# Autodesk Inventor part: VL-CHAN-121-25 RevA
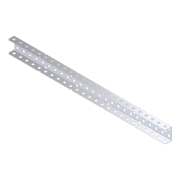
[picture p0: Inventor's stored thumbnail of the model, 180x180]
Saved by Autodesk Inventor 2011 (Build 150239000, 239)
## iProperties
Created: 2007-12
Part Number: VL-CHAN-121-25 RevA
Document SubType Name: Modeling
Density: 1 g/cm^3
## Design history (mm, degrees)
feature "Base1"
sketch "Sketch1"
  geometry: L1 (62.031, 0)-(0, 0) reference; L2 (62.031, 21.438)-(62.031, 0) reference; L3 (0, 21.438)-(62.031, 21.438) reference; L4 (-1.469, 19.794)-(0, 21.438) reference; L5 (-2.937, 21.438)-(-1.469, 19.794) reference; L6 (-63.5, 21.438)-(-2.937, 21.438) reference; L7 (-64.969, 19.794)-(-63.5, 21.438) reference; L8 (-66.437, 21.438)-(-64.969, 19.794) reference; L9 (-127, 21.438)-(-66.437, 21.438) reference; L10 (-128.469, 19.794)-(-127, 21.438) reference; L11 (-129.937, 21.438)-(-128.469, 19.794) reference; L12 (-190.5, 21.438)-(-129.937, 21.438) reference; L13 (-191.969, 19.794)-(-190.5, 21.438) reference; L14 (-193.437, 21.438)-(-191.969, 19.794) reference; L15 (-255.469, 21.438)-(-193.437, 21.438) reference; L16 (-255.469, 0)-(-255.469, 21.438) reference; L17 (-193.437, 0)-(-255.469, 0) reference; L18 (-191.969, 1.643)-(-193.437, 0) reference; L19 (-190.5, 0)-(-191.969, 1.643) reference; L20 (-129.937, 0)-(-190.5, 0) reference; L21 (-128.469, 1.643)-(-129.937, 0) reference; L22 (-127, 0)-(-128.469, 1.643) reference; L23 (-66.437, 0)-(-127, 0) reference; L24 (-64.969, 1.643)-(-66.437, 0) reference; L25 (-63.5, 0)-(-64.969, 1.643) reference; L26 (-2.937, 0)-(-63.5, 0) reference; L27 (-1.469, 1.643)-(-2.937, 0) reference; L28 (0, 0)-(-1.469, 1.643) reference; L29 (51.135, 13.03)-(47.528, 13.03) reference; L30 (51.643, 8.915)-(51.643, 12.522) reference; L31 (47.528, 8.407)-(51.135, 8.407) reference; L32 (47.02, 12.522)-(47.02, 8.915) reference; L33 (38.435, 13.03)-(34.828, 13.03) reference; L34 (38.943, 8.915)-(38.943, 12.522) reference; L35 (34.828, 8.407)-(38.435, 8.407) reference; L36 (34.32, 12.522)-(34.32, 8.915) reference; L37 (25.735, 13.03)-(22.128, 13.03) reference; L38 (26.243, 8.915)-(26.243, 12.522) reference; L39 (22.128, 8.407)-(25.735, 8.407) reference; L40 (21.62, 12.522)-(21.62, 8.915) reference; L41 (13.035, 13.03)-(9.428, 13.03) reference; L42 (13.543, 8.915)-(13.543, 12.522) reference; L43 (9.428, 8.407)-(13.035, 8.407) reference; L44 (8.92, 12.522)-(8.92, 8.915) reference; L45 (0.335, 13.03)-(-3.272, 13.03) reference; L46 (0.843, 8.915)-(0.843, 12.522) reference; L47 (-3.272, 8.407)-(0.335, 8.407) reference; L48 (-3.78, 12.522)-(-3.78, 8.915) reference; L49 (-12.365, 13.03)-(-15.972, 13.03) reference; L50 (-11.857, 8.915)-(-11.857, 12.522) reference; L51 (-15.972, 8.407)-(-12.365, 8.407) reference; L52 (-16.48, 12.522)-(-16.48, 8.915) reference; L53 (-25.065, 13.03)-(-28.672, 13.03) reference; L54 (-24.557, 8.915)-(-24.557, 12.522) reference; L55 (-28.672, 8.407)-(-25.065, 8.407) reference; L56 (-29.18, 12.522)-(-29.18, 8.915) reference; L57 (-37.765, 13.03)-(-41.372, 13.03) reference; L58 (-37.257, 8.915)-(-37.257, 12.522) reference; L59 (-41.372, 8.407)-(-37.765, 8.407) reference; L60 (-41.88, 12.522)-(-41.88, 8.915) reference; L61 (-50.465, 13.03)-(-54.072, 13.03) reference; L62 (-49.957, 8.915)-(-49.957, 12.522) reference; L63 (-54.072, 8.407)-(-50.465, 8.407) reference; L64 (-54.58, 12.522)-(-54.58, 8.915) reference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; C1 r 2.311 at (49.331, 10.719); C2 r 2.311 at (36.631, 10.719); C3 r 2.311 at (23.931, 10.719); C4 r 2.311 at (11.231, 10.719); C5 r 2.311 at (-1.469, 10.719); C6 r 2.311 at (-14.169, 10.719); C7 r 2.311 at (-26.869, 10.719); C8 r 2.311 at (-39.569, 10.719); C9 r 2.311 at (-52.269, 10.719); C10 r 2.311 at (-64.969, 10.719); C11 r 2.311 at (-77.669, 10.719); C12 r 2.311 at (-90.369, 10.719); C13 r 2.311 at (-103.069, 10.719); C14 r 2.311 at (-115.769, 10.719); C15 r 2.311 at (-128.469, 10.719); C16 r 2.311 at (-141.169, 10.719); C17 r 2.311 at (-153.869, 10.719); C18 r 2.311 at (-166.569, 10.719); C19 r 2.311 at (-179.269, 10.719); C20 r 2.311 at (-191.969, 10.719); C21 r 2.311 at (-204.669, 10.719); C22 r 2.311 at (-217.369, 10.719); C23 r 2.311 at (-230.069, 10.719); C24 r 2.311 at (-242.769, 10.719); A1 r 0.508 centre (47.528, 12.522) between (47.528, 13.03) and (47.02, 12.522) reference; A2 r 0.508 centre (51.135, 12.522) between (51.643, 12.522) and (51.135, 13.03) reference; A3 r 0.508 centre (51.135, 8.915) between (51.135, 8.407) and (51.643, 8.915) reference; A4 r 0.508 centre (47.528, 8.915) between (47.02, 8.915) and (47.528, 8.407) reference; A5 r 0.508 centre (34.828, 12.522) between (34.828, 13.03) and (34.32, 12.522) reference; A6 r 0.508 centre (38.435, 12.522) between (38.943, 12.522) and (38.435, 13.03) reference; A7 r 0.508 centre (38.435, 8.915) between (38.435, 8.407) and (38.943, 8.915) reference; A8 r 0.508 centre (34.828, 8.915) between (34.32, 8.915) and (34.828, 8.407) reference; A9 r 0.508 centre (22.128, 12.522) between (22.128, 13.03) and (21.62, 12.522) reference; A10 r 0.508 centre (25.735, 12.522) between (26.243, 12.522) and (25.735, 13.03) reference; A11 r 0.508 centre (25.735, 8.915) between (25.735, 8.407) and (26.243, 8.915) reference; A12 r 0.508 centre (22.128, 8.915) between (21.62, 8.915) and (22.128, 8.407) reference; A13 r 0.508 centre (9.428, 12.522) between (9.428, 13.03) and (8.92, 12.522) reference; A14 r 0.508 centre (13.035, 12.522) between (13.543, 12.522) and (13.035, 13.03) reference; A15 r 0.508 centre (13.035, 8.915) between (13.035, 8.407) and (13.543, 8.915) reference; A16 r 0.508 centre (9.428, 8.915) between (8.92, 8.915) and (9.428, 8.407) reference; A17 r 0.508 centre (-3.272, 12.522) between (-3.272, 13.03) and (-3.78, 12.522) reference; A18 r 0.508 centre (0.335, 12.522) between (0.843, 12.522) and (0.335, 13.03) reference; A19 r 0.508 centre (0.335, 8.915) between (0.335, 8.407) and (0.843, 8.915) reference; A20 r 0.508 centre (-3.272, 8.915) between (-3.78, 8.915) and (-3.272, 8.407) reference; A21 r 0.508 centre (-15.972, 12.522) between (-15.972, 13.03) and (-16.48, 12.522) reference; A22 r 0.508 centre (-12.365, 12.522) between (-11.857, 12.522) and (-12.365, 13.03) reference; A23 r 0.508 centre (-12.365, 8.915) between (-12.365, 8.407) and (-11.857, 8.915) reference; A24 r 0.508 centre (-15.972, 8.915) between (-16.48, 8.915) and (-15.972, 8.407) reference; A25 r 0.508 centre (-28.672, 12.522) between (-28.672, 13.03) and (-29.18, 12.522) reference; A26 r 0.508 centre (-25.065, 12.522) between (-24.557, 12.522) and (-25.065, 13.03) reference; A27 r 0.508 centre (-25.065, 8.915) between (-25.065, 8.407) and (-24.557, 8.915) reference; A28 r 0.508 centre (-28.672, 8.915) between (-29.18, 8.915) and (-28.672, 8.407) reference; A29 r 0.508 centre (-41.372, 12.522) between (-41.372, 13.03) and (-41.88, 12.522) reference; A30 r 0.508 centre (-37.765, 12.522) between (-37.257, 12.522) and (-37.765, 13.03) reference; A31 r 0.508 centre (-37.765, 8.915) between (-37.765, 8.407) and (-37.257, 8.915) reference; A32 r 0.508 centre (-41.372, 8.915) between (-41.88, 8.915) and (-41.372, 8.407) reference; A33 r 0.508 centre (-54.072, 12.522) between (-54.072, 13.03) and (-54.58, 12.522) reference; A34 r 0.508 centre (-50.465, 12.522) between (-49.957, 12.522) and (-50.465, 13.03) reference; A35 r 0.508 centre (-50.465, 8.915) between (-50.465, 8.407) and (-49.957, 8.915) reference; A36 r 0.508 centre (-54.072, 8.915) between (-54.58, 8.915) and (-54.072, 8.407) reference; A37 r 0.508 centre (-66.772, 12.522) between (-66.772, 13.03) and (-67.28, 12.522) reference; A38 r 0.508 centre (-63.165, 12.522) between (-62.657, 12.522) and (-63.165, 13.03) reference; A39 r 0.508 centre (-63.165, 8.915) between (-63.165, 8.407) and (-62.657, 8.915) reference; A40 r 0.508 centre (-66.772, 8.915) between (-67.28, 8.915) and (-66.772, 8.407) reference; A41 r 0.508 centre (-79.472, 12.522) between (-79.472, 13.03) and (-79.98, 12.522) reference; A42 r 0.508 centre (-75.865, 12.522) between (-75.357, 12.522) and (-75.865, 13.03) reference; A43 r 0.508 centre (-75.865, 8.915) between (-75.865, 8.407) and (-75.357, 8.915) reference; A44 r 0.508 centre (-79.472, 8.915) between (-79.98, 8.915) and (-79.472, 8.407) reference; A45 r 0.508 centre (-92.172, 12.522) between (-92.172, 13.03) and (-92.68, 12.522) reference; A46 r 0.508 centre (-88.565, 12.522) between (-88.057, 12.522) and (-88.565, 13.03) reference; A47 r 0.508 centre (-88.565, 8.915) between (-88.565, 8.407) and (-88.057, 8.915) reference; A48 r 0.508 centre (-92.172, 8.915) between (-92.68, 8.915) and (-92.172, 8.407) reference; A49 r 0.508 centre (-104.872, 12.522) between (-104.872, 13.03) and (-105.38, 12.522) reference; A50 r 0.508 centre (-101.265, 12.522) between (-100.757, 12.522) and (-101.265, 13.03) reference; A51 r 0.508 centre (-101.265, 8.915) between (-101.265, 8.407) and (-100.757, 8.915) reference; A52 r 0.508 centre (-104.872, 8.915) between (-105.38, 8.915) and (-104.872, 8.407) reference; A53 r 0.508 centre (-117.572, 12.522) between (-117.572, 13.03) and (-118.08, 12.522) reference; A54 r 0.508 centre (-113.965, 12.522) between (-113.457, 12.522) and (-113.965, 13.03) reference; A55 r 0.508 centre (-113.965, 8.915) between (-113.965, 8.407) and (-113.457, 8.915) reference; A56 r 0.508 centre (-117.572, 8.915) between (-118.08, 8.915) and (-117.572, 8.407) reference; A57 r 0.508 centre (-130.272, 12.522) between (-130.272, 13.03) and (-130.78, 12.522) reference; A58 r 0.508 centre (-126.665, 12.522) between (-126.157, 12.522) and (-126.665, 13.03) reference; A59 r 0.508 centre (-126.665, 8.915) between (-126.665, 8.407) and (-126.157, 8.915) reference; A60 r 0.508 centre (-130.272, 8.915) between (-130.78, 8.915) and (-130.272, 8.407) reference; A61 r 0.508 centre (-142.972, 12.522) between (-142.972, 13.03) and (-143.48, 12.522) reference; A62 r 0.508 centre (-139.365, 12.522) between (-138.857, 12.522) and (-139.365, 13.03) reference; A63 r 0.508 centre (-139.365, 8.915) between (-139.365, 8.407) and (-138.857, 8.915) reference; A64 r 0.508 centre (-142.972, 8.915) between (-143.48, 8.915) and (-142.972, 8.407) reference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
  constraints: 24 centre point, 3 tangent, 1 horizontal, 46 other
  dimensions: "d2" = 12.7 distance of C1.centre C2.centre
sketch "Sketch2" dims "d12" = 25.4
  geometry: L1 (-1.469, -9.86)-(0.558, -11.887) reference; L2 (0.558, -11.887)-(60.406, -11.887) reference; L3 (60.406, -11.887)-(62.031, -10.262) reference; L4 (62.031, -10.262)-(62.031, 0) reference; L5 (0, 0)-(62.031, 0) reference; L6 (-1.469, -1.643)-(0, 0) reference; L7 (-1.469, -1.643)-(-2.937, 0) reference; L8 (-63.5, 0)-(-2.937, 0) reference; L9 (-64.969, -1.643)-(-63.5, 0) reference; L10 (-64.969, -1.643)-(-66.437, 0) reference; L11 (-127, 0)-(-66.437, 0) reference; L12 (-128.469, -1.643)-(-127, 0) reference; L13 (-129.937, 0)-(-128.469, -1.643) reference; L14 (-190.5, 0)-(-129.937, 0) reference; L15 (-191.969, -1.643)-(-190.5, 0) reference; L16 (-191.969, -1.643)-(-193.437, 0) reference; L17 (-255.469, 0)-(-193.437, 0) reference; L18 (-255.469, 0)-(-255.469, -10.262) reference; L19 (-255.469, -10.262)-(-253.843, -11.887) reference; L20 (-253.843, -11.887)-(-193.995, -11.887) reference; L21 (-191.969, -9.86)-(-193.995, -11.887) reference; L22 (-191.969, -9.86)-(-189.942, -11.887) reference; L23 (-189.942, -11.887)-(-130.495, -11.887) reference; L24 (-128.469, -9.86)-(-130.495, -11.887) reference; L25 (-126.442, -11.887)-(-128.469, -9.86) reference; L26 (-126.442, -11.887)-(-66.995, -11.887) reference; L27 (-64.969, -9.86)-(-66.995, -11.887) reference; L28 (-64.969, -9.86)-(-62.942, -11.887) reference; L29 (-62.942, -11.887)-(-3.495, -11.887) reference; L30 (-1.469, -9.86)-(-3.495, -11.887) reference; L31 (-251.43, -7.341)-(-251.43, -3.734) reference; L32 (-250.922, -3.226)-(-247.315, -3.226) reference; L33 (-246.807, -3.734)-(-246.807, -7.341) reference; L34 (-247.315, -7.849)-(-250.922, -7.849) reference; L35 (-238.73, -7.341)-(-238.73, -3.734) reference; L36 (-238.222, -3.226)-(-234.615, -3.226) reference; L37 (-234.107, -3.734)-(-234.107, -7.341) reference; L38 (-234.615, -7.849)-(-238.222, -7.849) reference; L39 (-226.03, -7.341)-(-226.03, -3.734) reference; L40 (-225.522, -3.226)-(-221.915, -3.226) reference; L41 (-221.407, -3.734)-(-221.407, -7.341) reference; L42 (-221.915, -7.849)-(-225.522, -7.849) reference; L43 (-213.33, -7.341)-(-213.33, -3.734) reference; L44 (-212.822, -3.226)-(-209.215, -3.226) reference; L45 (-208.707, -3.734)-(-208.707, -7.341) reference; L46 (-209.215, -7.849)-(-212.822, -7.849) reference; L47 (-200.63, -7.341)-(-200.63, -3.734) reference; L48 (-200.122, -3.226)-(-196.515, -3.226) reference; L49 (-196.007, -3.734)-(-196.007, -7.341) reference; L50 (-196.515, -7.849)-(-200.122, -7.849) reference; L51 (-187.93, -7.341)-(-187.93, -3.734) reference; L52 (-187.422, -3.226)-(-183.815, -3.226) reference; L53 (-183.307, -3.734)-(-183.307, -7.341) reference; L54 (-183.815, -7.849)-(-187.422, -7.849) reference; L55 (-175.23, -7.341)-(-175.23, -3.734) reference; L56 (-174.722, -3.226)-(-171.115, -3.226) reference; L57 (-170.607, -3.734)-(-170.607, -7.341) reference; L58 (-171.115, -7.849)-(-174.722, -7.849) reference; L59 (-162.53, -7.341)-(-162.53, -3.734) reference; L60 (-162.022, -3.226)-(-158.415, -3.226) reference; L61 (-157.907, -3.734)-(-157.907, -7.341) reference; L62 (-158.415, -7.849)-(-162.022, -7.849) reference; L63 (-149.83, -7.341)-(-149.83, -3.734) reference; L64 (-149.322, -3.226)-(-145.715, -3.226) reference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; C1 r 2.311 at (55.681, -5.537); C2 r 2.311 at (42.981, -5.537); C3 r 2.311 at (30.281, -5.537); C4 r 2.311 at (17.581, -5.537); C5 r 2.311 at (4.881, -5.537); C6 r 2.311 at (-7.819, -5.537); C7 r 2.311 at (-20.519, -5.537); C8 r 2.311 at (-33.219, -5.537); C9 r 2.311 at (-45.919, -5.537); C10 r 2.311 at (-58.619, -5.537); C11 r 2.311 at (-71.319, -5.537); C12 r 2.311 at (-84.019, -5.537); C13 r 2.311 at (-96.719, -5.537); C14 r 2.311 at (-109.419, -5.537); C15 r 2.311 at (-122.119, -5.537); C16 r 2.311 at (-134.819, -5.537); C17 r 2.311 at (-147.519, -5.537); C18 r 2.311 at (-160.219, -5.537); C19 r 2.311 at (-172.919, -5.537); C20 r 2.311 at (-185.619, -5.537); C21 r 2.311 at (-198.319, -5.537); C22 r 2.311 at (-211.019, -5.537); C23 r 2.311 at (-223.719, -5.537); C24 r 2.311 at (-236.419, -5.537); C25 r 2.311 at (-249.119, -5.537); A1 r 0.508 centre (-250.922, -7.341) between (-251.43, -7.341) and (-250.922, -7.849) reference; A2 r 0.508 centre (-250.922, -3.734) between (-250.922, -3.226) and (-251.43, -3.734) reference; A3 r 0.508 centre (-247.315, -3.734) between (-246.807, -3.734) and (-247.315, -3.226) reference; A4 r 0.508 centre (-247.315, -7.341) between (-247.315, -7.849) and (-246.807, -7.341) reference; A5 r 0.508 centre (-238.222, -7.341) between (-238.73, -7.341) and (-238.222, -7.849) reference; A6 r 0.508 centre (-238.222, -3.734) between (-238.222, -3.226) and (-238.73, -3.734) reference; A7 r 0.508 centre (-234.615, -3.734) between (-234.107, -3.734) and (-234.615, -3.226) reference; A8 r 0.508 centre (-234.615, -7.341) between (-234.615, -7.849) and (-234.107, -7.341) reference; A9 r 0.508 centre (-225.522, -7.341) between (-226.03, -7.341) and (-225.522, -7.849) reference; A10 r 0.508 centre (-225.522, -3.734) between (-225.522, -3.226) and (-226.03, -3.734) reference; A11 r 0.508 centre (-221.915, -3.734) between (-221.407, -3.734) and (-221.915, -3.226) reference; A12 r 0.508 centre (-221.915, -7.341) between (-221.915, -7.849) and (-221.407, -7.341) reference; A13 r 0.508 centre (-212.822, -7.341) between (-213.33, -7.341) and (-212.822, -7.849) reference; A14 r 0.508 centre (-212.822, -3.734) between (-212.822, -3.226) and (-213.33, -3.734) reference; A15 r 0.508 centre (-209.215, -3.734) between (-208.707, -3.734) and (-209.215, -3.226) reference; A16 r 0.508 centre (-209.215, -7.341) between (-209.215, -7.849) and (-208.707, -7.341) reference; A17 r 0.508 centre (-200.122, -7.341) between (-200.63, -7.341) and (-200.122, -7.849) reference; A18 r 0.508 centre (-200.122, -3.734) between (-200.122, -3.226) and (-200.63, -3.734) reference; A19 r 0.508 centre (-196.515, -3.734) between (-196.007, -3.734) and (-196.515, -3.226) reference; A20 r 0.508 centre (-196.515, -7.341) between (-196.515, -7.849) and (-196.007, -7.341) reference; A21 r 0.508 centre (-187.422, -7.341) between (-187.93, -7.341) and (-187.422, -7.849) reference; A22 r 0.508 centre (-187.422, -3.734) between (-187.422, -3.226) and (-187.93, -3.734) reference; A23 r 0.508 centre (-183.815, -3.734) between (-183.307, -3.734) and (-183.815, -3.226) reference; A24 r 0.508 centre (-183.815, -7.341) between (-183.815, -7.849) and (-183.307, -7.341) reference; A25 r 0.508 centre (-174.722, -7.341) between (-175.23, -7.341) and (-174.722, -7.849) reference; A26 r 0.508 centre (-174.722, -3.734) between (-174.722, -3.226) and (-175.23, -3.734) reference; A27 r 0.508 centre (-171.115, -3.734) between (-170.607, -3.734) and (-171.115, -3.226) reference; A28 r 0.508 centre (-171.115, -7.341) between (-171.115, -7.849) and (-170.607, -7.341) reference; A29 r 0.508 centre (-162.022, -7.341) between (-162.53, -7.341) and (-162.022, -7.849) reference; A30 r 0.508 centre (-162.022, -3.734) between (-162.022, -3.226) and (-162.53, -3.734) reference; A31 r 0.508 centre (-158.415, -3.734) between (-157.907, -3.734) and (-158.415, -3.226) reference; A32 r 0.508 centre (-158.415, -7.341) between (-158.415, -7.849) and (-157.907, -7.341) reference; A33 r 0.508 centre (-149.322, -7.341) between (-149.83, -7.341) and (-149.322, -7.849) reference; A34 r 0.508 centre (-149.322, -3.734) between (-149.322, -3.226) and (-149.83, -3.734) reference; A35 r 0.508 centre (-145.715, -3.734) between (-145.207, -3.734) and (-145.715, -3.226) reference; A36 r 0.508 centre (-145.715, -7.341) between (-145.715, -7.849) and (-145.207, -7.341) reference; A37 r 0.508 centre (-136.622, -7.341) between (-137.13, -7.341) and (-136.622, -7.849) reference; A38 r 0.508 centre (-136.622, -3.734) between (-136.622, -3.226) and (-137.13, -3.734) reference; A39 r 0.508 centre (-133.015, -3.734) between (-132.507, -3.734) and (-133.015, -3.226) reference; A40 r 0.508 centre (-133.015, -7.341) between (-133.015, -7.849) and (-132.507, -7.341) reference; A41 r 0.508 centre (-123.922, -7.341) between (-124.43, -7.341) and (-123.922, -7.849) reference; A42 r 0.508 centre (-123.922, -3.734) between (-123.922, -3.226) and (-124.43, -3.734) reference; A43 r 0.508 centre (-120.315, -3.734) between (-119.807, -3.734) and (-120.315, -3.226) reference; A44 r 0.508 centre (-120.315, -7.341) between (-120.315, -7.849) and (-119.807, -7.341) reference; A45 r 0.508 centre (-111.222, -7.341) between (-111.73, -7.341) and (-111.222, -7.849) reference; A46 r 0.508 centre (-111.222, -3.734) between (-111.222, -3.226) and (-111.73, -3.734) reference; A47 r 0.508 centre (-107.615, -3.734) between (-107.107, -3.734) and (-107.615, -3.226) reference; A48 r 0.508 centre (-107.615, -7.341) between (-107.615, -7.849) and (-107.107, -7.341) reference; A49 r 0.508 centre (-98.522, -7.341) between (-99.03, -7.341) and (-98.522, -7.849) reference; A50 r 0.508 centre (-98.522, -3.734) between (-98.522, -3.226) and (-99.03, -3.734) reference; A51 r 0.508 centre (-94.915, -3.734) between (-94.407, -3.734) and (-94.915, -3.226) reference; A52 r 0.508 centre (-94.915, -7.341) between (-94.915, -7.849) and (-94.407, -7.341) reference; A53 r 0.508 centre (-85.822, -7.341) between (-86.33, -7.341) and (-85.822, -7.849) reference; A54 r 0.508 centre (-85.822, -3.734) between (-85.822, -3.226) and (-86.33, -3.734) reference; A55 r 0.508 centre (-82.215, -3.734) between (-81.707, -3.734) and (-82.215, -3.226) reference; A56 r 0.508 centre (-82.215, -7.341) between (-82.215, -7.849) and (-81.707, -7.341) reference; A57 r 0.508 centre (-73.122, -7.341) between (-73.63, -7.341) and (-73.122, -7.849) reference; A58 r 0.508 centre (-73.122, -3.734) between (-73.122, -3.226) and (-73.63, -3.734) reference; A59 r 0.508 centre (-69.515, -3.734) between (-69.007, -3.734) and (-69.515, -3.226) reference; A60 r 0.508 centre (-69.515, -7.341) between (-69.515, -7.849) and (-69.007, -7.341) reference; A61 r 0.508 centre (-60.422, -7.341) between (-60.93, -7.341) and (-60.422, -7.849) reference; A62 r 0.508 centre (-60.422, -3.734) between (-60.422, -3.226) and (-60.93, -3.734) reference; A63 r 0.508 centre (-56.815, -3.734) between (-56.307, -3.734) and (-56.815, -3.226) reference; A64 r 0.508 centre (-56.815, -7.341) between (-56.815, -7.849) and (-56.307, -7.341) reference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
  constraints: 25 centre point, 7 tangent, 1 horizontal, 46 other
  dimensions: "d9" = 12.7 distance of C1.centre C2.centre
sketch "Sketch3" dims "d19" = 25.4
  geometry: L1 (-189.942, -11.887)-(-130.495, -11.887) reference; L2 (-128.469, -9.86)-(-130.495, -11.887) reference; L3 (-126.442, -11.887)-(-128.469, -9.86) reference; L4 (-126.442, -11.887)-(-66.995, -11.887) reference; L5 (-64.969, -9.86)-(-66.995, -11.887) reference; L6 (-62.942, -11.887)-(-64.969, -9.86) reference; L7 (-62.942, -11.887)-(-3.495, -11.887) reference; L8 (-1.469, -9.86)-(-3.495, -11.887) reference; L9 (-1.469, -9.86)-(0.558, -11.887) reference; L10 (0.558, -11.887)-(60.406, -11.887) reference; L11 (60.406, -11.887)-(62.031, -10.262) reference; L12 (62.031, -10.262)-(62.031, 0) reference; L13 (0, 0)-(62.031, 0) reference; L14 (-1.469, -1.643)-(0, 0) reference; L15 (-2.937, 0)-(-1.469, -1.643) reference; L16 (-63.5, 0)-(-2.937, 0) reference; L17 (-64.969, -1.643)-(-63.5, 0) reference; L18 (-66.437, 0)-(-64.969, -1.643) reference; L19 (-127, 0)-(-66.437, 0) reference; L20 (-128.469, -1.643)-(-127, 0) reference; L21 (-129.937, 0)-(-128.469, -1.643) reference; L22 (-190.5, 0)-(-129.937, 0) reference; L23 (-191.969, -1.643)-(-190.5, 0) reference; L24 (-193.437, 0)-(-191.969, -1.643) reference; L25 (-255.469, 0)-(-193.437, 0) reference; L26 (-255.469, 0)-(-255.469, -10.262) reference; L27 (-255.469, -10.262)-(-253.843, -11.887) reference; L28 (-253.843, -11.887)-(-193.995, -11.887) reference; L29 (-191.969, -9.86)-(-193.995, -11.887) reference; L30 (-189.942, -11.887)-(-191.969, -9.86) reference; L31 (53.878, -3.226)-(57.485, -3.226) reference; L32 (57.993, -3.734)-(57.993, -7.341) reference; L33 (57.485, -7.849)-(53.878, -7.849) reference; L34 (53.37, -7.341)-(53.37, -3.734) reference; L35 (41.178, -3.226)-(44.785, -3.226) reference; L36 (45.293, -3.734)-(45.293, -7.341) reference; L37 (44.785, -7.849)-(41.178, -7.849) reference; L38 (40.67, -7.341)-(40.67, -3.734) reference; L39 (28.478, -3.226)-(32.085, -3.226) reference; L40 (32.593, -3.734)-(32.593, -7.341) reference; L41 (32.085, -7.849)-(28.478, -7.849) reference; L42 (27.97, -7.341)-(27.97, -3.734) reference; L43 (15.778, -3.226)-(19.385, -3.226) reference; L44 (19.893, -3.734)-(19.893, -7.341) reference; L45 (19.385, -7.849)-(15.778, -7.849) reference; L46 (15.27, -7.341)-(15.27, -3.734) reference; L47 (3.078, -3.226)-(6.685, -3.226) reference; L48 (7.193, -3.734)-(7.193, -7.341) reference; L49 (6.685, -7.849)-(3.078, -7.849) reference; L50 (2.57, -7.341)-(2.57, -3.734) reference; L51 (-9.622, -3.226)-(-6.015, -3.226) reference; L52 (-5.507, -3.734)-(-5.507, -7.341) reference; L53 (-6.015, -7.849)-(-9.622, -7.849) reference; L54 (-10.13, -7.341)-(-10.13, -3.734) reference; L55 (-22.322, -3.226)-(-18.715, -3.226) reference; L56 (-18.207, -3.734)-(-18.207, -7.341) reference; L57 (-18.715, -7.849)-(-22.322, -7.849) reference; L58 (-22.83, -7.341)-(-22.83, -3.734) reference; L59 (-35.022, -3.226)-(-31.415, -3.226) reference; L60 (-30.907, -3.734)-(-30.907, -7.341) reference; L61 (-31.415, -7.849)-(-35.022, -7.849) reference; L62 (-35.53, -7.341)-(-35.53, -3.734) reference; L63 (-47.722, -3.226)-(-44.115, -3.226) reference; L64 (-43.607, -3.734)-(-43.607, -7.341) reference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; C1 r 2.311 at (-249.119, -5.537); C2 r 2.311 at (-236.419, -5.537); C3 r 2.311 at (-223.719, -5.537); C4 r 2.311 at (-211.019, -5.537); C5 r 2.311 at (-198.319, -5.537); C6 r 2.311 at (-185.619, -5.537); C7 r 2.311 at (-172.919, -5.537); C8 r 2.311 at (-160.219, -5.537); C9 r 2.311 at (-147.519, -5.537); C10 r 2.311 at (-134.819, -5.537); C11 r 2.311 at (-122.119, -5.537); C12 r 2.311 at (-109.419, -5.537); C13 r 2.311 at (-96.719, -5.537); C14 r 2.311 at (-84.019, -5.537); C15 r 2.311 at (-71.319, -5.537); C16 r 2.311 at (-58.619, -5.537); C17 r 2.311 at (-45.919, -5.537); C18 r 2.311 at (-33.219, -5.537); C19 r 2.311 at (-20.519, -5.537); C20 r 2.311 at (-7.819, -5.537); C21 r 2.311 at (4.881, -5.537); C22 r 2.311 at (17.581, -5.537); C23 r 2.311 at (30.281, -5.537); C24 r 2.311 at (42.981, -5.537); A1 r 0.508 centre (53.878, -3.734) between (53.878, -3.226) and (53.37, -3.734) reference; A2 r 0.508 centre (57.485, -3.734) between (57.993, -3.734) and (57.485, -3.226) reference; A3 r 0.508 centre (57.485, -7.341) between (57.485, -7.849) and (57.993, -7.341) reference; A4 r 0.508 centre (53.878, -7.341) between (53.37, -7.341) and (53.878, -7.849) reference; A5 r 0.508 centre (41.178, -3.734) between (41.178, -3.226) and (40.67, -3.734) reference; A6 r 0.508 centre (44.785, -3.734) between (45.293, -3.734) and (44.785, -3.226) reference; A7 r 0.508 centre (44.785, -7.341) between (44.785, -7.849) and (45.293, -7.341) reference; A8 r 0.508 centre (41.178, -7.341) between (40.67, -7.341) and (41.178, -7.849) reference; A9 r 0.508 centre (28.478, -3.734) between (28.478, -3.226) and (27.97, -3.734) reference; A10 r 0.508 centre (32.085, -3.734) between (32.593, -3.734) and (32.085, -3.226) reference; A11 r 0.508 centre (32.085, -7.341) between (32.085, -7.849) and (32.593, -7.341) reference; A12 r 0.508 centre (28.478, -7.341) between (27.97, -7.341) and (28.478, -7.849) reference; A13 r 0.508 centre (15.778, -3.734) between (15.778, -3.226) and (15.27, -3.734) reference; A14 r 0.508 centre (19.385, -3.734) between (19.893, -3.734) and (19.385, -3.226) reference; A15 r 0.508 centre (19.385, -7.341) between (19.385, -7.849) and (19.893, -7.341) reference; A16 r 0.508 centre (15.778, -7.341) between (15.27, -7.341) and (15.778, -7.849) reference; A17 r 0.508 centre (3.078, -3.734) between (3.078, -3.226) and (2.57, -3.734) reference; A18 r 0.508 centre (6.685, -3.734) between (7.193, -3.734) and (6.685, -3.226) reference; A19 r 0.508 centre (6.685, -7.341) between (6.685, -7.849) and (7.193, -7.341) reference; A20 r 0.508 centre (3.078, -7.341) between (2.57, -7.341) and (3.078, -7.849) reference; A21 r 0.508 centre (-9.622, -3.734) between (-9.622, -3.226) and (-10.13, -3.734) reference; A22 r 0.508 centre (-6.015, -3.734) between (-5.507, -3.734) and (-6.015, -3.226) reference; A23 r 0.508 centre (-6.015, -7.341) between (-6.015, -7.849) and (-5.507, -7.341) reference; A24 r 0.508 centre (-9.622, -7.341) between (-10.13, -7.341) and (-9.622, -7.849) reference; A25 r 0.508 centre (-22.322, -3.734) between (-22.322, -3.226) and (-22.83, -3.734) reference; A26 r 0.508 centre (-18.715, -3.734) between (-18.207, -3.734) and (-18.715, -3.226) reference; A27 r 0.508 centre (-18.715, -7.341) between (-18.715, -7.849) and (-18.207, -7.341) reference; A28 r 0.508 centre (-22.322, -7.341) between (-22.83, -7.341) and (-22.322, -7.849) reference; A29 r 0.508 centre (-35.022, -3.734) between (-35.022, -3.226) and (-35.53, -3.734) reference; A30 r 0.508 centre (-31.415, -3.734) between (-30.907, -3.734) and (-31.415, -3.226) reference; A31 r 0.508 centre (-31.415, -7.341) between (-31.415, -7.849) and (-30.907, -7.341) reference; A32 r 0.508 centre (-35.022, -7.341) between (-35.53, -7.341) and (-35.022, -7.849) reference; A33 r 0.508 centre (-47.722, -3.734) between (-47.722, -3.226) and (-48.23, -3.734) reference; A34 r 0.508 centre (-44.115, -3.734) between (-43.607, -3.734) and (-44.115, -3.226) reference; A35 r 0.508 centre (-44.115, -7.341) between (-44.115, -7.849) and (-43.607, -7.341) reference; A36 r 0.508 centre (-47.722, -7.341) between (-48.23, -7.341) and (-47.722, -7.849) reference; A37 r 0.508 centre (-60.422, -3.734) between (-60.422, -3.226) and (-60.93, -3.734) reference; A38 r 0.508 centre (-56.815, -3.734) between (-56.307, -3.734) and (-56.815, -3.226) reference; A39 r 0.508 centre (-56.815, -7.341) between (-56.815, -7.849) and (-56.307, -7.341) reference; A40 r 0.508 centre (-60.422, -7.341) between (-60.93, -7.341) and (-60.422, -7.849) reference; A41 r 0.508 centre (-73.122, -3.734) between (-73.122, -3.226) and (-73.63, -3.734) reference; A42 r 0.508 centre (-69.515, -3.734) between (-69.007, -3.734) and (-69.515, -3.226) reference; A43 r 0.508 centre (-69.515, -7.341) between (-69.515, -7.849) and (-69.007, -7.341) reference; A44 r 0.508 centre (-73.122, -7.341) between (-73.63, -7.341) and (-73.122, -7.849) reference; A45 r 0.508 centre (-85.822, -3.734) between (-85.822, -3.226) and (-86.33, -3.734) reference; A46 r 0.508 centre (-82.215, -3.734) between (-81.707, -3.734) and (-82.215, -3.226) reference; A47 r 0.508 centre (-82.215, -7.341) between (-82.215, -7.849) and (-81.707, -7.341) reference; A48 r 0.508 centre (-85.822, -7.341) between (-86.33, -7.341) and (-85.822, -7.849) reference; A49 r 0.508 centre (-98.522, -3.734) between (-98.522, -3.226) and (-99.03, -3.734) reference; A50 r 0.508 centre (-94.915, -3.734) between (-94.407, -3.734) and (-94.915, -3.226) reference; A51 r 0.508 centre (-94.915, -7.341) between (-94.915, -7.849) and (-94.407, -7.341) reference; A52 r 0.508 centre (-98.522, -7.341) between (-99.03, -7.341) and (-98.522, -7.849) reference; A53 r 0.508 centre (-111.222, -3.734) between (-111.222, -3.226) and (-111.73, -3.734) reference; A54 r 0.508 centre (-107.615, -3.734) between (-107.107, -3.734) and (-107.615, -3.226) reference; A55 r 0.508 centre (-107.615, -7.341) between (-107.615, -7.849) and (-107.107, -7.341) reference; A56 r 0.508 centre (-111.222, -7.341) between (-111.73, -7.341) and (-111.222, -7.849) reference; A57 r 0.508 centre (-123.922, -3.734) between (-123.922, -3.226) and (-124.43, -3.734) reference; A58 r 0.508 centre (-120.315, -3.734) between (-119.807, -3.734) and (-120.315, -3.226) reference; A59 r 0.508 centre (-120.315, -7.341) between (-120.315, -7.849) and (-119.807, -7.341) reference; A60 r 0.508 centre (-123.922, -7.341) between (-124.43, -7.341) and (-123.922, -7.849) reference; A61 r 0.508 centre (-136.622, -3.734) between (-136.622, -3.226) and (-137.13, -3.734) reference; A62 r 0.508 centre (-133.015, -3.734) between (-132.507, -3.734) and (-133.015, -3.226) reference; A63 r 0.508 centre (-133.015, -7.341) between (-133.015, -7.849) and (-132.507, -7.341) reference; A64 r 0.508 centre (-136.622, -7.341) between (-137.13, -7.341) and (-136.622, -7.849) reference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
  constraints: 24 centre point, 4 tangent, 1 horizontal, 46 other
  dimensions: "d16" = 12.7 distance of C1.centre C2.centre
workplane "Work Plane1"
body "Solid1"
other parameters: "d5" = 25.4
